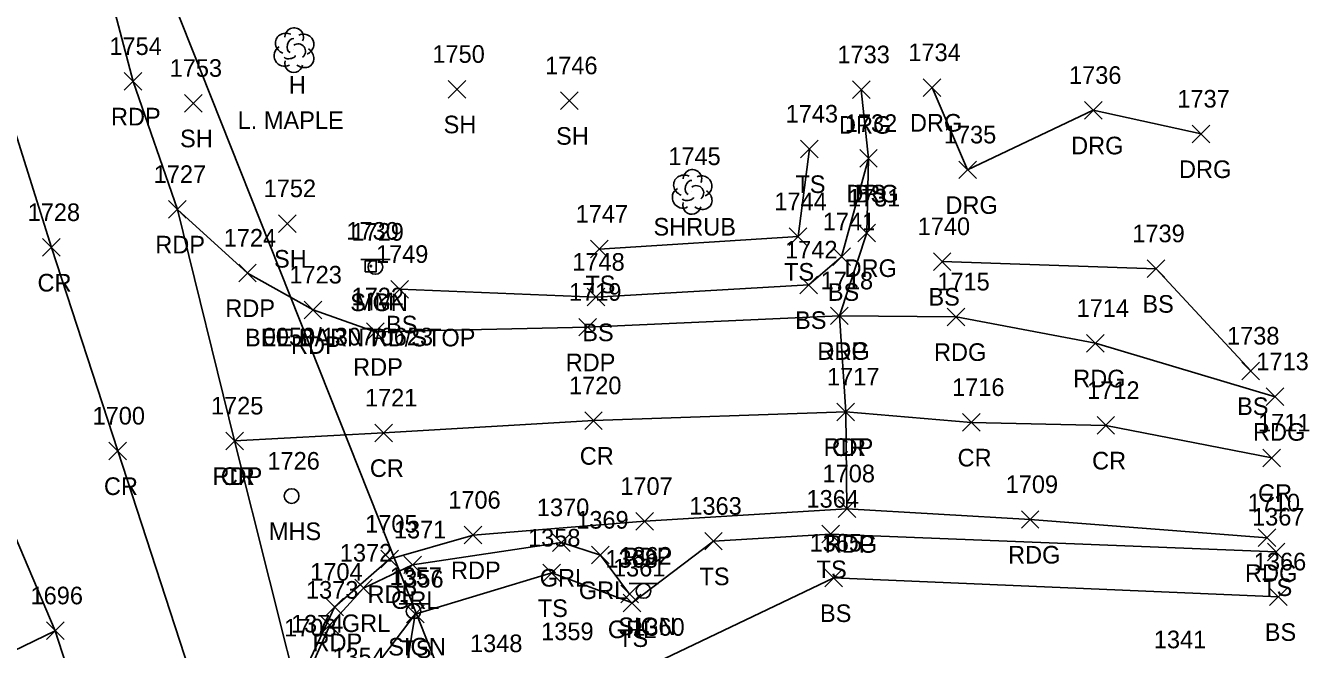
# Model space of a CAD drawing. Extents: x 1620157 to 1620595, y 115111 to 117885.
# Drawn here: x 1620300.9 to 1620446.6, y 115477.3 to 115548.1 of the extents above; entities that cross this region are included whole.
import ezdxf

# ---------------------------------------------------------------- set-up
doc = ezdxf.new("R2010")
doc.units = 0
for name, color, linetype in [('DCP', 7, 'Continuous'), ('L_A', 7, 'Continuous'), ('L_C', 7, 'Continuous'), ('L_I', 7, 'Continuous'), ('L_TIC', 7, 'Continuous'), ('LELB', 7, 'Continuous'), ('LSH', 7, 'Continuous'), ('LTD', 7, 'Continuous'), ('P_A', 7, 'Continuous'), ('P_I', 7, 'Continuous'), ('P_TIC', 7, 'Continuous'), ('PET', 7, 'Continuous'), ('PEU', 7, 'Continuous'), ('PRC', 7, 'Continuous'), ('R_A', 7, 'Continuous'), ('R_I', 7, 'Continuous'), ('R_TIC', 7, 'Continuous'), ('RDG', 7, 'Continuous'), ('RGR', 7, 'Continuous'), ('S_A', 7, 'Continuous'), ('S_C', 7, 'Continuous'), ('S_I', 7, 'Continuous'), ('SRM', 7, 'Continuous'), ('SSGN', 7, 'Continuous'), ('U_A', 7, 'Continuous'), ('U_I', 7, 'Continuous'), ('USMH', 7, 'Continuous')]:
    doc.layers.add(name, color=color, linetype=linetype)

msp = doc.modelspace()

# ---------------------------------------------------------------- linework, layer by layer
at = {"layer": 'DCP'}
msp.add_lwpolyline([(1620352.15, 115463.88), (1620299.44, 115596.57)], dxfattribs=at)
at = {"layer": 'L_TIC'}
for points in [[(1620348.82, 115539.87), (1620350.82, 115541.87)], [(1620350.82, 115539.87), (1620348.82, 115541.87)], [(1620318.9, 115538.28), (1620320.9, 115540.28)], [(1620320.9, 115538.28), (1620318.9, 115540.28)], [(1620361.59, 115538.57), (1620363.59, 115540.57)], [(1620363.59, 115538.57), (1620361.59, 115540.57)], [(1620388.84, 115533.09), (1620390.84, 115535.09)], [(1620390.84, 115533.09), (1620388.84, 115535.09)], [(1620395.55, 115532.02), (1620397.55, 115534.02)], [(1620397.55, 115532.02), (1620395.55, 115534.02)], [(1620329.57, 115524.62), (1620331.57, 115526.62)], [(1620331.57, 115524.62), (1620329.57, 115526.62)], [(1620387.55, 115523.14), (1620389.55, 115525.14)], [(1620389.55, 115523.14), (1620387.55, 115525.14)], [(1620364.99, 115521.72), (1620366.99, 115523.72)], [(1620366.99, 115521.72), (1620364.99, 115523.72)], [(1620392.49, 115520.85), (1620394.49, 115522.85)], [(1620394.49, 115520.85), (1620392.49, 115522.85)], [(1620403.91, 115520.31), (1620405.91, 115522.31)], [(1620405.91, 115520.31), (1620403.91, 115522.31)], [(1620428.2, 115519.5), (1620430.2, 115521.5)], [(1620430.2, 115519.5), (1620428.2, 115521.5)], [(1620342.33, 115517.16), (1620344.33, 115519.16)], [(1620344.33, 115517.16), (1620342.33, 115519.16)], [(1620388.77, 115517.66), (1620390.77, 115519.66)], [(1620390.77, 115517.66), (1620388.77, 115519.66)], [(1620364.61, 115516.27), (1620366.61, 115518.27)], [(1620366.61, 115516.27), (1620364.61, 115518.27)], [(1620438.94, 115507.89), (1620440.94, 115509.89)], [(1620440.94, 115507.89), (1620438.94, 115509.89)], [(1620391.25, 115489.37), (1620393.25, 115491.37)], [(1620393.25, 115489.37), (1620391.25, 115491.37)], [(1620377.95, 115488.57), (1620379.95, 115490.57)], [(1620379.95, 115488.57), (1620377.95, 115490.57)], [(1620441.83, 115487.34), (1620443.83, 115489.34)], [(1620443.83, 115487.34), (1620441.83, 115489.34)], [(1620359.59, 115484.96), (1620361.59, 115486.96)], [(1620361.59, 115484.96), (1620359.59, 115486.96)], [(1620391.6, 115484.39), (1620393.6, 115486.39)], [(1620393.6, 115484.39), (1620391.6, 115486.39)], [(1620442.08, 115482.25), (1620444.08, 115484.25)], [(1620444.08, 115482.25), (1620442.08, 115484.25)], [(1620368.71, 115481.56), (1620370.71, 115483.56)], [(1620370.71, 115481.56), (1620368.71, 115483.56)], [(1620344.1, 115480.3), (1620346.1, 115482.3)], [(1620346.1, 115480.3), (1620344.1, 115482.3)], [(1620344.1, 115480.3), (1620346.1, 115482.3)], [(1620346.1, 115480.3), (1620344.1, 115482.3)]]:
    msp.add_lwpolyline(points, dxfattribs=at)
at = {"layer": 'LELB'}
for points in [[(1620389.84, 115534.09), (1620388.55, 115524.14), (1620365.99, 115522.72)], [(1620396.55, 115533.02), (1620393.49, 115521.85), (1620389.77, 115518.66), (1620365.61, 115517.27), (1620343.33, 115518.16)], [(1620439.94, 115508.89), (1620429.2, 115520.5), (1620404.91, 115521.31)], [(1620337.62, 115458.02), (1620338.39, 115472.46), (1620345.1, 115481.3), (1620360.59, 115485.96), (1620369.71, 115482.56), (1620378.95, 115489.57), (1620392.25, 115490.37), (1620442.83, 115488.34)], [(1620353.28, 115465.35), (1620354, 115473.97), (1620362.09, 115475.33), (1620372.56, 115475.83), (1620392.6, 115485.39), (1620443.08, 115483.25)], [(1620342.04, 115462.87), (1620345.1, 115481.3)]]:
    msp.add_lwpolyline(points, dxfattribs=at)
at = {"layer": 'LSH'}
msp.add_line((1620376.51, 115529.26), (1620376.51, 115529.26), dxfattribs=at)
msp.add_line((1620376.51, 115529.26), (1620376.51, 115529.26), dxfattribs=at)
msp.add_arc((1620376.56, 115530.7), 1.05, 335.5272, 180.9563, dxfattribs=at)
for centre, major_axis, ratio, start_param, end_param in [((1620375.72, 115529.93), (1.21, -0.51), 0.895232, 1.570796, 4.712389), ((1620376.3, 115529.72), (-0.208, -0.792), 0.645439, 3.141593, 6.283185), ((1620377.55, 115529.85), (-1.14, -0.48), 0.949671, 1.570796, 4.712389), ((1620375.43, 115528.55), (0.58, -1.04), 0.959034, 3.141593, 6.283185), ((1620377.01, 115529.1), (-0.5, 0.667), 0.989748, 3.141593, 6.283185), ((1620377.51, 115528.43), (-1.09, 0.79), 0.841452, 1.570796, 4.712389), ((1620376.51, 115527.76), (0.26, 1.06), 0.942809, 1.570796, 4.712389), ((1620376.05, 115528.51), (-0.625, -0.083), 0.423636, 0, 3.141593)]:
    msp.add_ellipse(centre, major_axis=major_axis, ratio=ratio, start_param=start_param, end_param=end_param, dxfattribs=at)
at = {"layer": 'LTD'}
msp.add_line((1620331.31, 115545.36), (1620331.31, 115545.36), dxfattribs=at)
msp.add_line((1620331.31, 115545.36), (1620331.31, 115545.36), dxfattribs=at)
msp.add_arc((1620331.35, 115546.79), 1.05, 335.5272, 180.9563, dxfattribs=at)
for centre, major_axis, ratio, start_param, end_param in [((1620330.52, 115546.03), (1.21, -0.51), 0.895232, 1.570796, 4.712389), ((1620331.1, 115545.82), (-0.208, -0.792), 0.645439, 3.141593, 6.283185), ((1620332.35, 115545.94), (-1.14, -0.48), 0.949671, 1.570796, 4.712389), ((1620330.22, 115544.65), (0.58, -1.04), 0.959034, 3.141593, 6.283185), ((1620331.81, 115545.19), (-0.5, 0.667), 0.989748, 3.141593, 6.283185), ((1620332.31, 115544.53), (-1.09, 0.79), 0.841452, 1.570796, 4.712389), ((1620331.31, 115543.86), (0.26, 1.06), 0.942809, 1.570796, 4.712389), ((1620330.85, 115544.61), (-0.625, -0.083), 0.423636, 0, 3.141593)]:
    msp.add_ellipse(centre, major_axis=major_axis, ratio=ratio, start_param=start_param, end_param=end_param, dxfattribs=at)
at = {"layer": 'P_TIC'}
for points in [[(1620312.06, 115540.76), (1620314.06, 115542.76)], [(1620314.06, 115540.76), (1620312.06, 115542.76)], [(1620317.09, 115526.23), (1620319.09, 115528.23)], [(1620319.09, 115526.23), (1620317.09, 115528.23)], [(1620317.09, 115526.23), (1620319.09, 115528.23)], [(1620319.09, 115526.23), (1620317.09, 115528.23)], [(1620302.78, 115521.91), (1620304.78, 115523.91)], [(1620304.78, 115521.91), (1620302.78, 115523.91)], [(1620325.05, 115519.01), (1620327.05, 115521.01)], [(1620327.05, 115519.01), (1620325.05, 115521.01)], [(1620332.5, 115514.82), (1620334.5, 115516.82)], [(1620334.5, 115514.82), (1620332.5, 115516.82)], [(1620392.25, 115514.15), (1620394.25, 115516.15)], [(1620394.25, 115514.15), (1620392.25, 115516.15)], [(1620392.25, 115514.15), (1620394.25, 115516.15)], [(1620394.25, 115514.15), (1620392.25, 115516.15)], [(1620405.49, 115514.03), (1620407.49, 115516.03)], [(1620407.49, 115514.03), (1620405.49, 115516.03)], [(1620363.68, 115512.86), (1620365.68, 115514.86)], [(1620365.68, 115512.86), (1620363.68, 115514.86)], [(1620339.55, 115512.34), (1620341.55, 115514.34)], [(1620341.55, 115512.34), (1620339.55, 115514.34)], [(1620421.3, 115511.03), (1620423.3, 115513.03)], [(1620423.3, 115511.03), (1620421.3, 115513.03)], [(1620441.71, 115504.97), (1620443.71, 115506.97)], [(1620443.71, 115504.97), (1620441.71, 115506.97)], [(1620364.33, 115502.25), (1620366.33, 115504.25)], [(1620366.33, 115502.25), (1620364.33, 115504.25)], [(1620392.97, 115503.24), (1620394.97, 115505.24)], [(1620394.97, 115503.24), (1620392.97, 115505.24)], [(1620392.97, 115503.24), (1620394.97, 115505.24)], [(1620394.97, 115503.24), (1620392.97, 115505.24)], [(1620340.5, 115500.86), (1620342.5, 115502.86)], [(1620342.5, 115500.86), (1620340.5, 115502.86)], [(1620407.22, 115502.05), (1620409.22, 115504.05)], [(1620409.22, 115502.05), (1620407.22, 115504.05)], [(1620422.49, 115501.71), (1620424.49, 115503.71)], [(1620424.49, 115501.71), (1620422.49, 115503.71)], [(1620323.59, 115499.95), (1620325.59, 115501.95)], [(1620325.59, 115499.95), (1620323.59, 115501.95)], [(1620323.59, 115499.95), (1620325.59, 115501.95)], [(1620325.59, 115499.95), (1620323.59, 115501.95)], [(1620310.32, 115498.81), (1620312.32, 115500.81)], [(1620312.32, 115498.81), (1620310.32, 115500.81)], [(1620441.33, 115498.02), (1620443.33, 115500.02)], [(1620443.33, 115498.02), (1620441.33, 115500.02)], [(1620393.1, 115492.25), (1620395.1, 115494.25)], [(1620395.1, 115492.25), (1620393.1, 115494.25)], [(1620393.1, 115492.25), (1620395.1, 115494.25)], [(1620395.1, 115492.25), (1620393.1, 115494.25)], [(1620370.15, 115490.82), (1620372.15, 115492.82)], [(1620372.15, 115490.82), (1620370.15, 115492.82)], [(1620413.9, 115491.03), (1620415.9, 115493.03)], [(1620415.9, 115491.03), (1620413.9, 115493.03)], [(1620350.66, 115489.26), (1620352.66, 115491.26)], [(1620352.66, 115489.26), (1620350.66, 115491.26)], [(1620440.8, 115488.95), (1620442.8, 115490.95)], [(1620442.8, 115488.95), (1620440.8, 115490.95)], [(1620341.18, 115486.54), (1620343.18, 115488.54)], [(1620343.18, 115486.54), (1620341.18, 115488.54)], [(1620334.94, 115481.08), (1620336.94, 115483.08)], [(1620336.94, 115481.08), (1620334.94, 115483.08)], [(1620303.22, 115478.4), (1620305.22, 115480.4)], [(1620305.22, 115478.4), (1620303.22, 115480.4)], [(1620303.22, 115478.4), (1620305.22, 115480.4)], [(1620305.22, 115478.4), (1620303.22, 115480.4)]]:
    msp.add_lwpolyline(points, dxfattribs=at)
at = {"layer": 'PET'}
for points in [[(1620336.22, 115456.8), (1620332.52, 115469.32), (1620324.59, 115500.95), (1620318.09, 115527.23), (1620313.06, 115541.76), (1620309.74, 115554.43), (1620302.9, 115574.33), (1620297.63, 115590.44), (1620296.31, 115595.42), (1620295.45, 115598.55), (1620285.02, 115631.41), (1620284, 115634.58), (1620271.05, 115676.55), (1620263.94, 115701.46), (1620257.2, 115724.05), (1620247.86, 115755.87), (1620237.56, 115791.5), (1620229.87, 115820.37), (1620222.52, 115845.46)], [(1620320.14, 115439.39), (1620314.87, 115455.06), (1620309.06, 115464.39), (1620304.22, 115479.4), (1620297.09, 115496.09), (1620293.95, 115506.93), (1620292.02, 115512.47), (1620283.67, 115536.02), (1620274.58, 115564.81), (1620268.48, 115584.52), (1620253.11, 115635.23), (1620250.12, 115643.88), (1620242.65, 115668.01), (1620237.66, 115684.19), (1620235.08, 115693.76), (1620231.19, 115707.41), (1620225.41, 115727.43), (1620211.93, 115771.95), (1620203.83, 115799.04), (1620193.37, 115837.22)], [(1620332.52, 115469.32), (1620332.98, 115475.75), (1620335.94, 115482.08), (1620342.18, 115487.54), (1620351.66, 115490.26), (1620371.15, 115491.82), (1620394.1, 115493.25), (1620393.97, 115504.24), (1620393.25, 115515.15), (1620364.68, 115513.86), (1620340.55, 115513.34), (1620333.5, 115515.82), (1620326.05, 115520.01), (1620318.09, 115527.23)]]:
    msp.add_lwpolyline(points, dxfattribs=at)
at = {"layer": 'PEU'}
for points in [[(1620442.71, 115505.97), (1620422.3, 115512.03), (1620406.49, 115515.03), (1620393.25, 115515.15)], [(1620394.1, 115493.25), (1620414.9, 115492.03), (1620441.8, 115489.95)]]:
    msp.add_lwpolyline(points, dxfattribs=at)
at = {"layer": 'PRC'}
for points in [[(1620328.08, 115447.46), (1620322.14, 115466.61), (1620311.32, 115499.81), (1620303.78, 115522.91), (1620294.72, 115551.74), (1620279.31, 115600.23), (1620271.12, 115626.45), (1620257.91, 115669.49), (1620247.64, 115703.03), (1620242.45, 115719.65), (1620232.98, 115752.35), (1620223.66, 115784.04), (1620214.14, 115816.15), (1620207.47, 115841.18)], [(1620442.33, 115499.02), (1620423.49, 115502.71), (1620408.22, 115503.05), (1620393.97, 115504.24), (1620365.33, 115503.25), (1620341.5, 115501.86), (1620324.59, 115500.95)], [(1620223.71, 115439.52), (1620256.33, 115456.52), (1620276.36, 115465.6), (1620290.73, 115473.22), (1620294.64, 115474.78), (1620304.22, 115479.4)]]:
    msp.add_lwpolyline(points, dxfattribs=at)
at = {"layer": 'R_TIC'}
for points in [[(1620394.72, 115539.82), (1620396.72, 115541.82)], [(1620396.72, 115539.82), (1620394.72, 115541.82)], [(1620402.76, 115540.06), (1620404.76, 115542.06)], [(1620404.76, 115540.06), (1620402.76, 115542.06)], [(1620421.06, 115537.48), (1620423.06, 115539.48)], [(1620423.06, 115537.48), (1620421.06, 115539.48)], [(1620433.31, 115534.79), (1620435.31, 115536.79)], [(1620435.31, 115534.79), (1620433.31, 115536.79)], [(1620395.55, 115532.02), (1620397.55, 115534.02)], [(1620397.55, 115532.02), (1620395.55, 115534.02)], [(1620406.79, 115530.72), (1620408.79, 115532.72)], [(1620408.79, 115530.72), (1620406.79, 115532.72)], [(1620395.34, 115523.56), (1620397.34, 115525.56)], [(1620397.34, 115523.56), (1620395.34, 115525.56)], [(1620392.25, 115514.15), (1620394.25, 115516.15)], [(1620394.25, 115514.15), (1620392.25, 115516.15)], [(1620360.68, 115488.41), (1620362.68, 115490.41)], [(1620362.68, 115488.41), (1620360.68, 115490.41)], [(1620365.12, 115486.99), (1620367.12, 115488.99)], [(1620367.12, 115486.99), (1620365.12, 115488.99)], [(1620343.79, 115485.88), (1620345.79, 115487.88)], [(1620345.79, 115485.88), (1620343.79, 115487.88)], [(1620338.22, 115483.25), (1620340.22, 115485.25)], [(1620340.22, 115483.25), (1620338.22, 115485.25)], [(1620368.42, 115482.56), (1620370.42, 115484.56)], [(1620370.42, 115482.56), (1620368.42, 115484.56)], [(1620334.38, 115479.04), (1620336.38, 115481.04)], [(1620336.38, 115479.04), (1620334.38, 115481.04)]]:
    msp.add_lwpolyline(points, dxfattribs=at)
at = {"layer": 'RDG'}
for points in [[(1620393.25, 115515.15), (1620396.34, 115524.56), (1620396.55, 115533.02), (1620395.72, 115540.82)], [(1620403.76, 115541.06), (1620407.79, 115531.72), (1620422.06, 115538.48), (1620434.31, 115535.79)]]:
    msp.add_lwpolyline(points, dxfattribs=at)
at = {"layer": 'RGR'}
msp.add_lwpolyline([(1620369.42, 115483.56), (1620366.12, 115487.99), (1620361.68, 115489.41), (1620344.79, 115486.88), (1620339.22, 115484.25), (1620335.38, 115480.04), (1620333.68, 115476.2), (1620332.84, 115471.1), (1620333.34, 115467.78), (1620336.45, 115457.75)], dxfattribs=at)
at = {"layer": 'SRM'}
msp.add_lwpolyline([(1620339.42, 115521.41), (1620340.67, 115521.41), (1620340.67, 115520.16), (1620339.42, 115520.16)], close=True, dxfattribs=at)
msp.add_circle((1620340.05, 115520.79), 0.0833, dxfattribs=at)
at = {"layer": 'SSGN'}
for p, q in [((1620338.92, 115521.53), (1620342.26, 115521.53)), ((1620340.57, 115520.7), (1620340.57, 115520.7)), ((1620369.36, 115484.76), (1620372.69, 115484.76)), ((1620371.01, 115483.92), (1620371.01, 115483.92)), ((1620343.25, 115482.45), (1620346.58, 115482.45)), ((1620344.9, 115481.61), (1620344.9, 115481.61))]:
    msp.add_line(p, q, dxfattribs=at)
for centre in [(1620340.57, 115520.7), (1620371.01, 115483.92), (1620344.9, 115481.61)]:
    msp.add_circle(centre, 0.833, dxfattribs=at)
at = {"layer": 'USMH'}
for p, q in [((1620331.06, 115494.69), (1620331.06, 115494.69)), ((1620331.89, 115494.69), (1620331.89, 115494.69))]:
    msp.add_line(p, q, dxfattribs=at)
msp.add_circle((1620331.06, 115494.69), 0.833, dxfattribs=at)

# ---------------------------------------------------------------- texts
at = {"layer": 'L_A'}
for s, p in [('H', (1620330.74, 115540.36)), ('SH', (1620348.31, 115535.87)), ('SH', (1620318.39, 115534.28)), ('SH', (1620361.08, 115534.57)), ('TS', (1620388.25, 115529.09)), ('BS', (1620394.99, 115528.02)), ('SHRUB', (1620372.14, 115524.26)), ('SH', (1620329.06, 115520.62)), ('TS', (1620386.96, 115519.14)), ('TS', (1620364.4, 115517.72)), ('BS', (1620391.93, 115516.85)), ('BS', (1620403.35, 115516.31)), ('BS', (1620427.64, 115515.5)), ('BS', (1620341.77, 115513.16)), ('BS', (1620388.21, 115513.66)), ('BS', (1620364.05, 115512.27)), ('BS', (1620438.39, 115503.89)), ('TS', (1620390.66, 115485.37)), ('TS', (1620377.36, 115484.57)), ('TS', (1620441.24, 115483.34)), ('TS', (1620359, 115480.96)), ('BS', (1620391.04, 115480.39)), ('TS', (1620368.12, 115477.56)), ('BS', (1620441.53, 115478.25)), ('TS', (1620343.51, 115476.3)), ('TS', (1620343.51, 115476.3))]:
    msp.add_text(s, height=2, dxfattribs=at).set_placement(p)
at = {"layer": 'L_C'}
msp.add_text('L. MAPLE', height=2, dxfattribs=at).set_placement((1620324.93, 115536.36))
at = {"layer": 'L_I'}
for s, p in [('1750', (1620347.04, 115543.87)), ('1753', (1620317.21, 115542.28)), ('1746', (1620359.84, 115542.57)), ('1743', (1620387.14, 115537.09)), ('1732', (1620393.86, 115536.02)), ('1745', (1620373.82, 115532.26)), ('1752', (1620327.88, 115528.62)), ('1744', (1620385.86, 115527.14)), ('1747', (1620363.3, 115525.72)), ('1741', (1620391.36, 115524.85)), ('1740', (1620402.13, 115524.31)), ('1739', (1620426.5, 115523.5)), ('1749', (1620340.63, 115521.16)), ('1742', (1620387.08, 115521.66)), ('1748', (1620362.92, 115520.27)), ('1738', (1620437.25, 115511.89)), ('1363', (1620376.21, 115492.57)), ('1364', (1620389.51, 115493.37)), ('1367', (1620440.09, 115491.34)), ('1358', (1620357.9, 115488.96)), ('1365', (1620389.86, 115488.39)), ('1366', (1620440.29, 115486.25)), ('1361', (1620367.54, 115485.56)), ('1356', (1620342.36, 115484.3)), ('1356', (1620342.36, 115484.3)), ('1359', (1620359.39, 115478.33)), ('1360', (1620369.73, 115478.83)), ('1348', (1620351.31, 115476.97)), ('1354', (1620335.69, 115475.46))]:
    msp.add_text(s, height=2, dxfattribs=at).set_placement(p)
at = {"layer": 'P_A'}
for s, p in [('RDP', (1620310.55, 115536.76)), ('RDP', (1620315.58, 115522.23)), ('RDP', (1620315.58, 115522.23)), ('CR', (1620302.21, 115517.91)), ('RDP', (1620323.53, 115515.01)), ('RDP', (1620330.99, 115510.82)), ('RDG', (1620390.74, 115510.15)), ('RDP', (1620390.74, 115510.15)), ('RDG', (1620403.98, 115510.03)), ('RDP', (1620338.04, 115508.34)), ('RDP', (1620362.17, 115508.86)), ('RDG', (1620419.79, 115507.03)), ('RDG', (1620440.2, 115500.97)), ('CR', (1620363.77, 115498.25)), ('RDP', (1620391.45, 115499.24)), ('CR', (1620392.4, 115499.24)), ('CR', (1620406.66, 115498.05)), ('CR', (1620339.94, 115496.86)), ('CR', (1620421.93, 115497.71)), ('RDP', (1620322.08, 115495.95)), ('CR', (1620323.02, 115495.95)), ('CR', (1620309.75, 115494.81)), ('CR', (1620440.77, 115494.02)), ('RDG', (1620391.59, 115488.25)), ('RDP', (1620391.59, 115488.25)), ('RDP', (1620368.63, 115486.82)), ('RDG', (1620412.39, 115487.03)), ('RDP', (1620349.15, 115485.26)), ('RDG', (1620439.29, 115484.95)), ('RDP', (1620339.67, 115482.54)), ('RDP', (1620333.43, 115477.08))]:
    msp.add_text(s, height=2, dxfattribs=at).set_placement(p)
at = {"layer": 'P_I'}
for s, p in [('1754', (1620310.37, 115544.76)), ('1727', (1620315.4, 115530.23)), ('1727', (1620315.4, 115530.23)), ('1728', (1620301.09, 115525.91)), ('1724', (1620323.35, 115523.01)), ('1723', (1620330.81, 115518.82)), ('1719', (1620362.55, 115516.86)), ('1718', (1620391.12, 115518.15)), ('1718', (1620391.12, 115518.15)), ('1715', (1620404.36, 115518.03)), ('1722', (1620337.86, 115516.34)), ('1714', (1620420.17, 115515.03)), ('1713', (1620440.58, 115508.97)), ('1717', (1620391.84, 115507.24)), ('1717', (1620391.84, 115507.24)), ('1720', (1620362.55, 115506.25)), ('1716', (1620406.04, 115506.05)), ('1712', (1620421.37, 115505.71)), ('1725', (1620321.9, 115503.95)), ('1725', (1620321.9, 115503.95)), ('1721', (1620339.38, 115504.86)), ('1700', (1620308.46, 115502.81)), ('1711', (1620440.77, 115502.02)), ('1708', (1620391.33, 115496.25)), ('1708', (1620391.33, 115496.25)), ('1709', (1620412.12, 115495.03)), ('1707', (1620368.37, 115494.82)), ('1706', (1620348.84, 115493.26)), ('1710', (1620439.59, 115492.95)), ('1705', (1620339.41, 115490.54)), ('1704', (1620333.17, 115485.08)), ('1696', (1620301.42, 115482.4)), ('1696', (1620301.42, 115482.4)), ('1703', (1620330.21, 115478.75))]:
    msp.add_text(s, height=2, dxfattribs=at).set_placement(p)
at = {"layer": 'R_A'}
for s, p in [('DRG', (1620393.2, 115535.82)), ('DRG', (1620401.25, 115536.06)), ('DRG', (1620419.55, 115533.48)), ('DRG', (1620431.8, 115530.79)), ('DRG', (1620394.04, 115528.02)), ('DRG', (1620405.28, 115526.72)), ('DRG', (1620393.83, 115519.56)), ('DRG', (1620390.74, 115510.15)), ('GRL', (1620359.22, 115484.41)), ('GRL', (1620342.34, 115481.88)), ('GRL', (1620363.67, 115482.99)), ('GRL', (1620336.76, 115479.25)), ('GRL', (1620366.96, 115478.56))]:
    msp.add_text(s, height=2, dxfattribs=at).set_placement(p)
at = {"layer": 'R_I'}
for s, p in [('1733', (1620393.02, 115543.82)), ('1734', (1620401.07, 115544.06)), ('1736', (1620419.31, 115541.48)), ('1737', (1620431.61, 115538.79)), ('1732', (1620393.86, 115536.02)), ('1735', (1620405.1, 115534.72)), ('1731', (1620394.21, 115527.56)), ('1718', (1620391.12, 115518.15)), ('1370', (1620358.9, 115492.41)), ('1369', (1620363.37, 115490.99)), ('1371', (1620342.67, 115489.88)), ('1372', (1620336.53, 115487.25)), ('1368', (1620366.68, 115486.56)), ('1373', (1620332.69, 115483.04)), ('1374', (1620330.98, 115479.2))]:
    msp.add_text(s, height=2, dxfattribs=at).set_placement(p)
at = {"layer": 'S_A'}
for s, p in [('SIGN', (1620337.71, 115515.68)), ('MM', (1620338.23, 115515.79)), ('SIGN', (1620368.14, 115478.9)), ('SIGN', (1620342.03, 115476.59))]:
    msp.add_text(s, height=2, dxfattribs=at).set_placement(p)
at = {"layer": 'S_C'}
for s, p in [('BEE BARN RD/STOP', (1620325.77, 115511.68)), ('0050/1307/0623', (1620327.78, 115511.79))]:
    msp.add_text(s, height=2, dxfattribs=at).set_placement(p)
at = {"layer": 'S_I'}
for s, p in [('1730', (1620337.27, 115523.79)), ('1729', (1620337.85, 115523.68)), ('1362', (1620368.25, 115486.9)), ('1357', (1620342.18, 115484.59))]:
    msp.add_text(s, height=2, dxfattribs=at).set_placement(p)
at = {"layer": 'U_A'}
msp.add_text('MHS', height=2, dxfattribs=at).set_placement((1620328.47, 115489.69))
at = {"layer": 'U_I'}
for s, p in [('1726', (1620328.31, 115497.69)), ('1341', (1620428.94, 115477.41))]:
    msp.add_text(s, height=2, dxfattribs=at).set_placement(p)

doc.saveas('drawing.dxf')
